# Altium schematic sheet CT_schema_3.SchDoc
size 573 x 363 mm
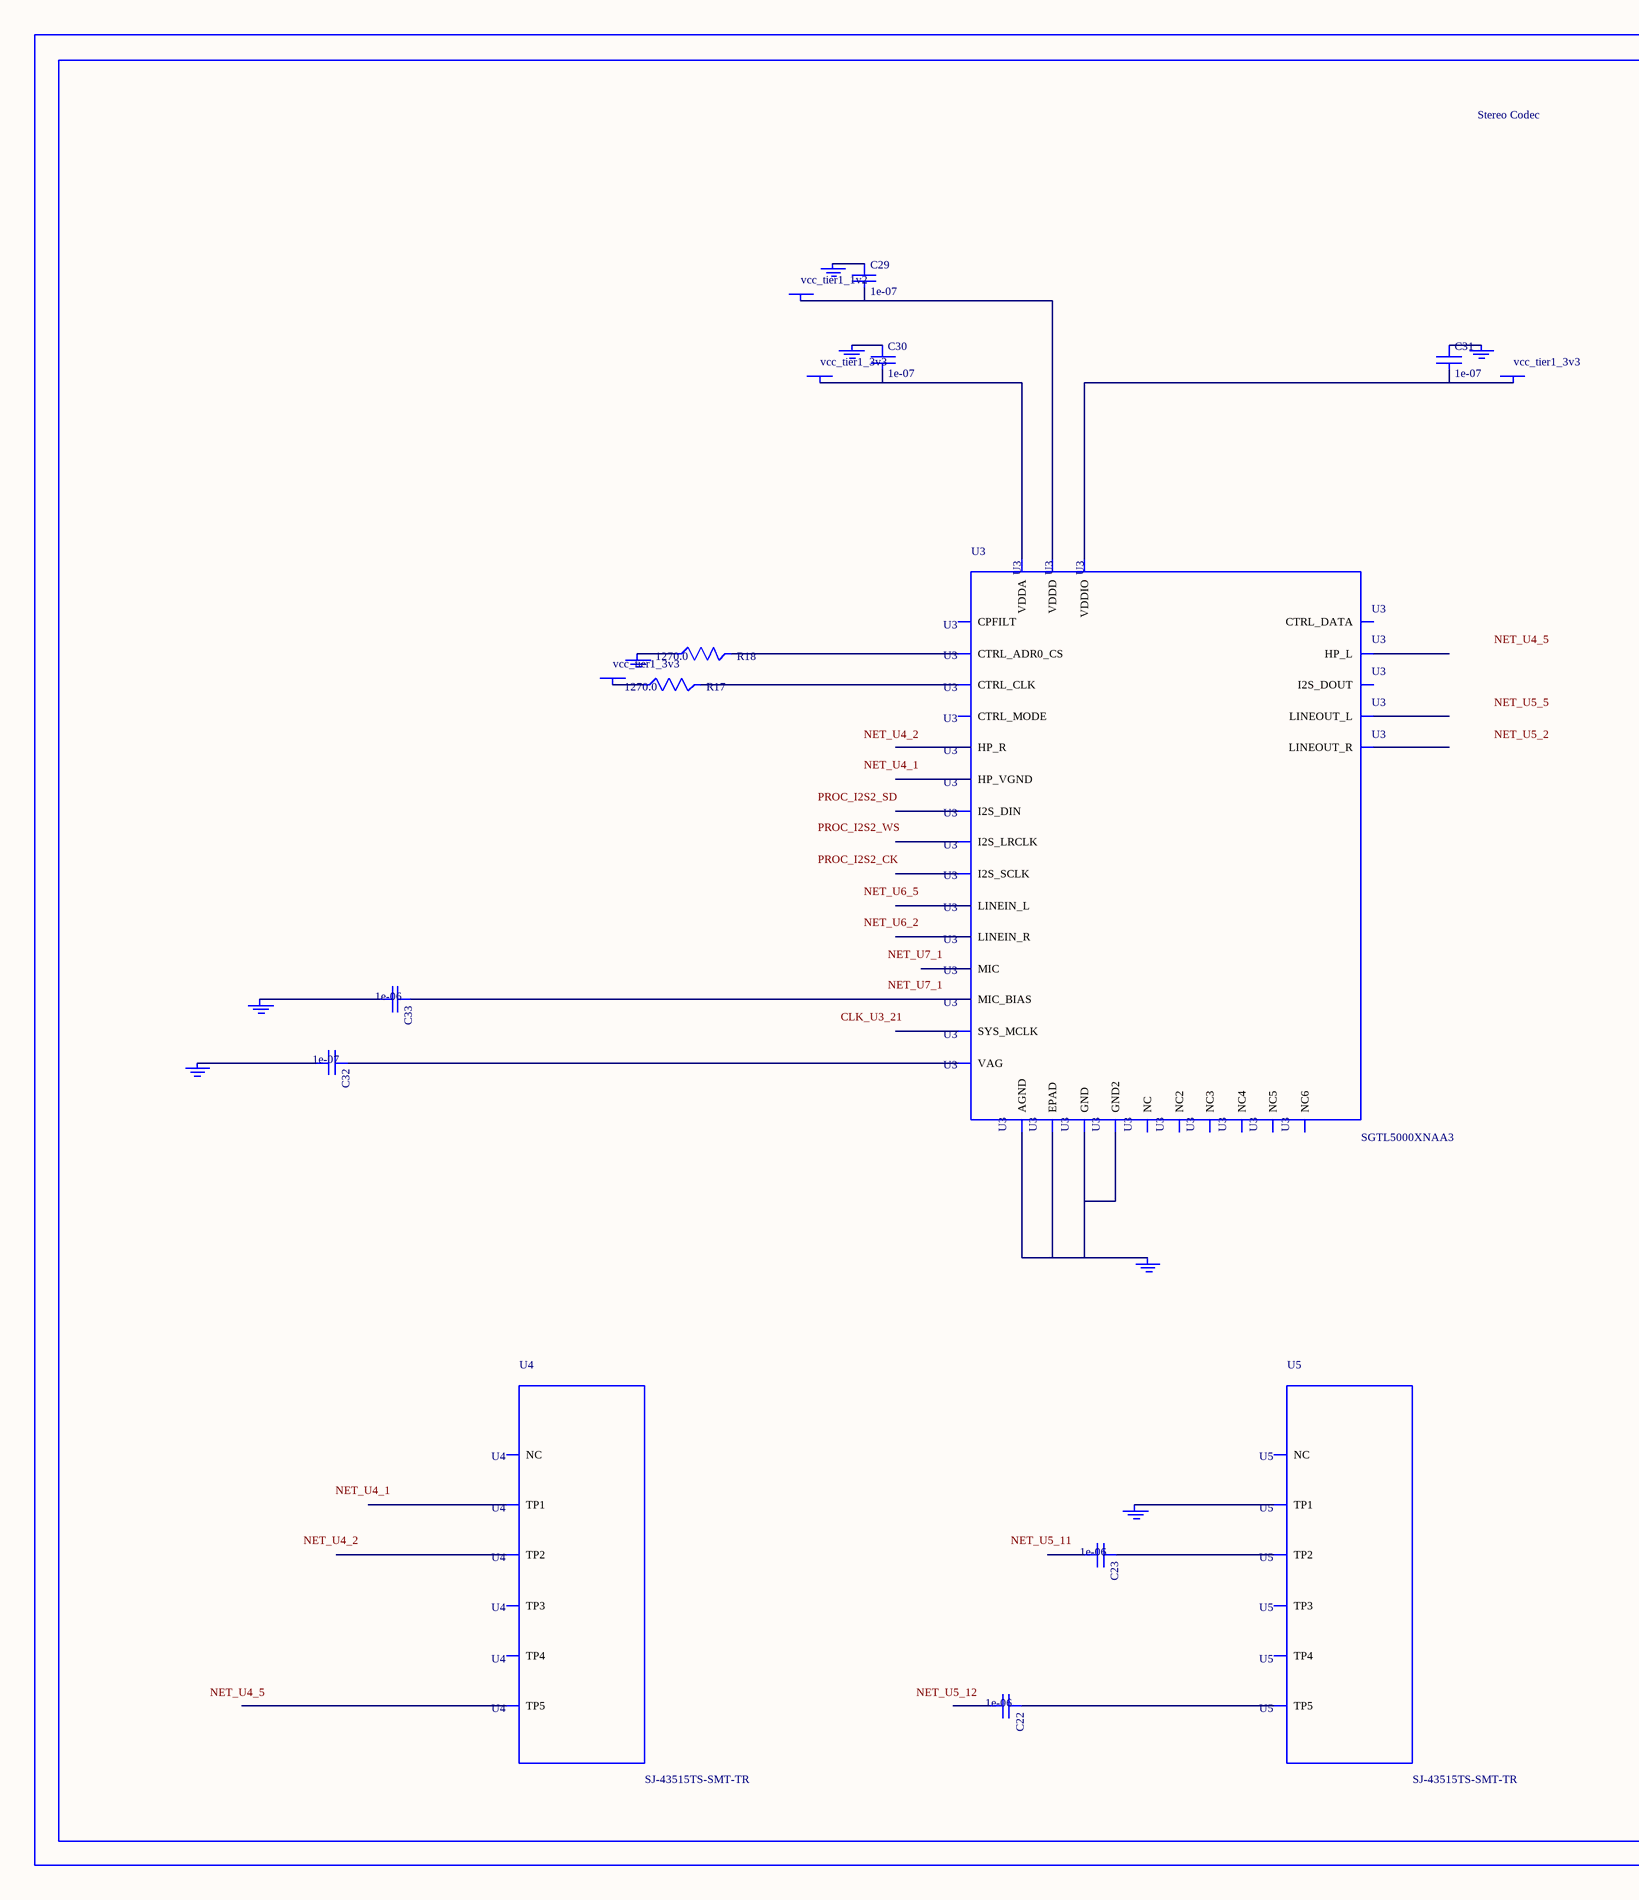
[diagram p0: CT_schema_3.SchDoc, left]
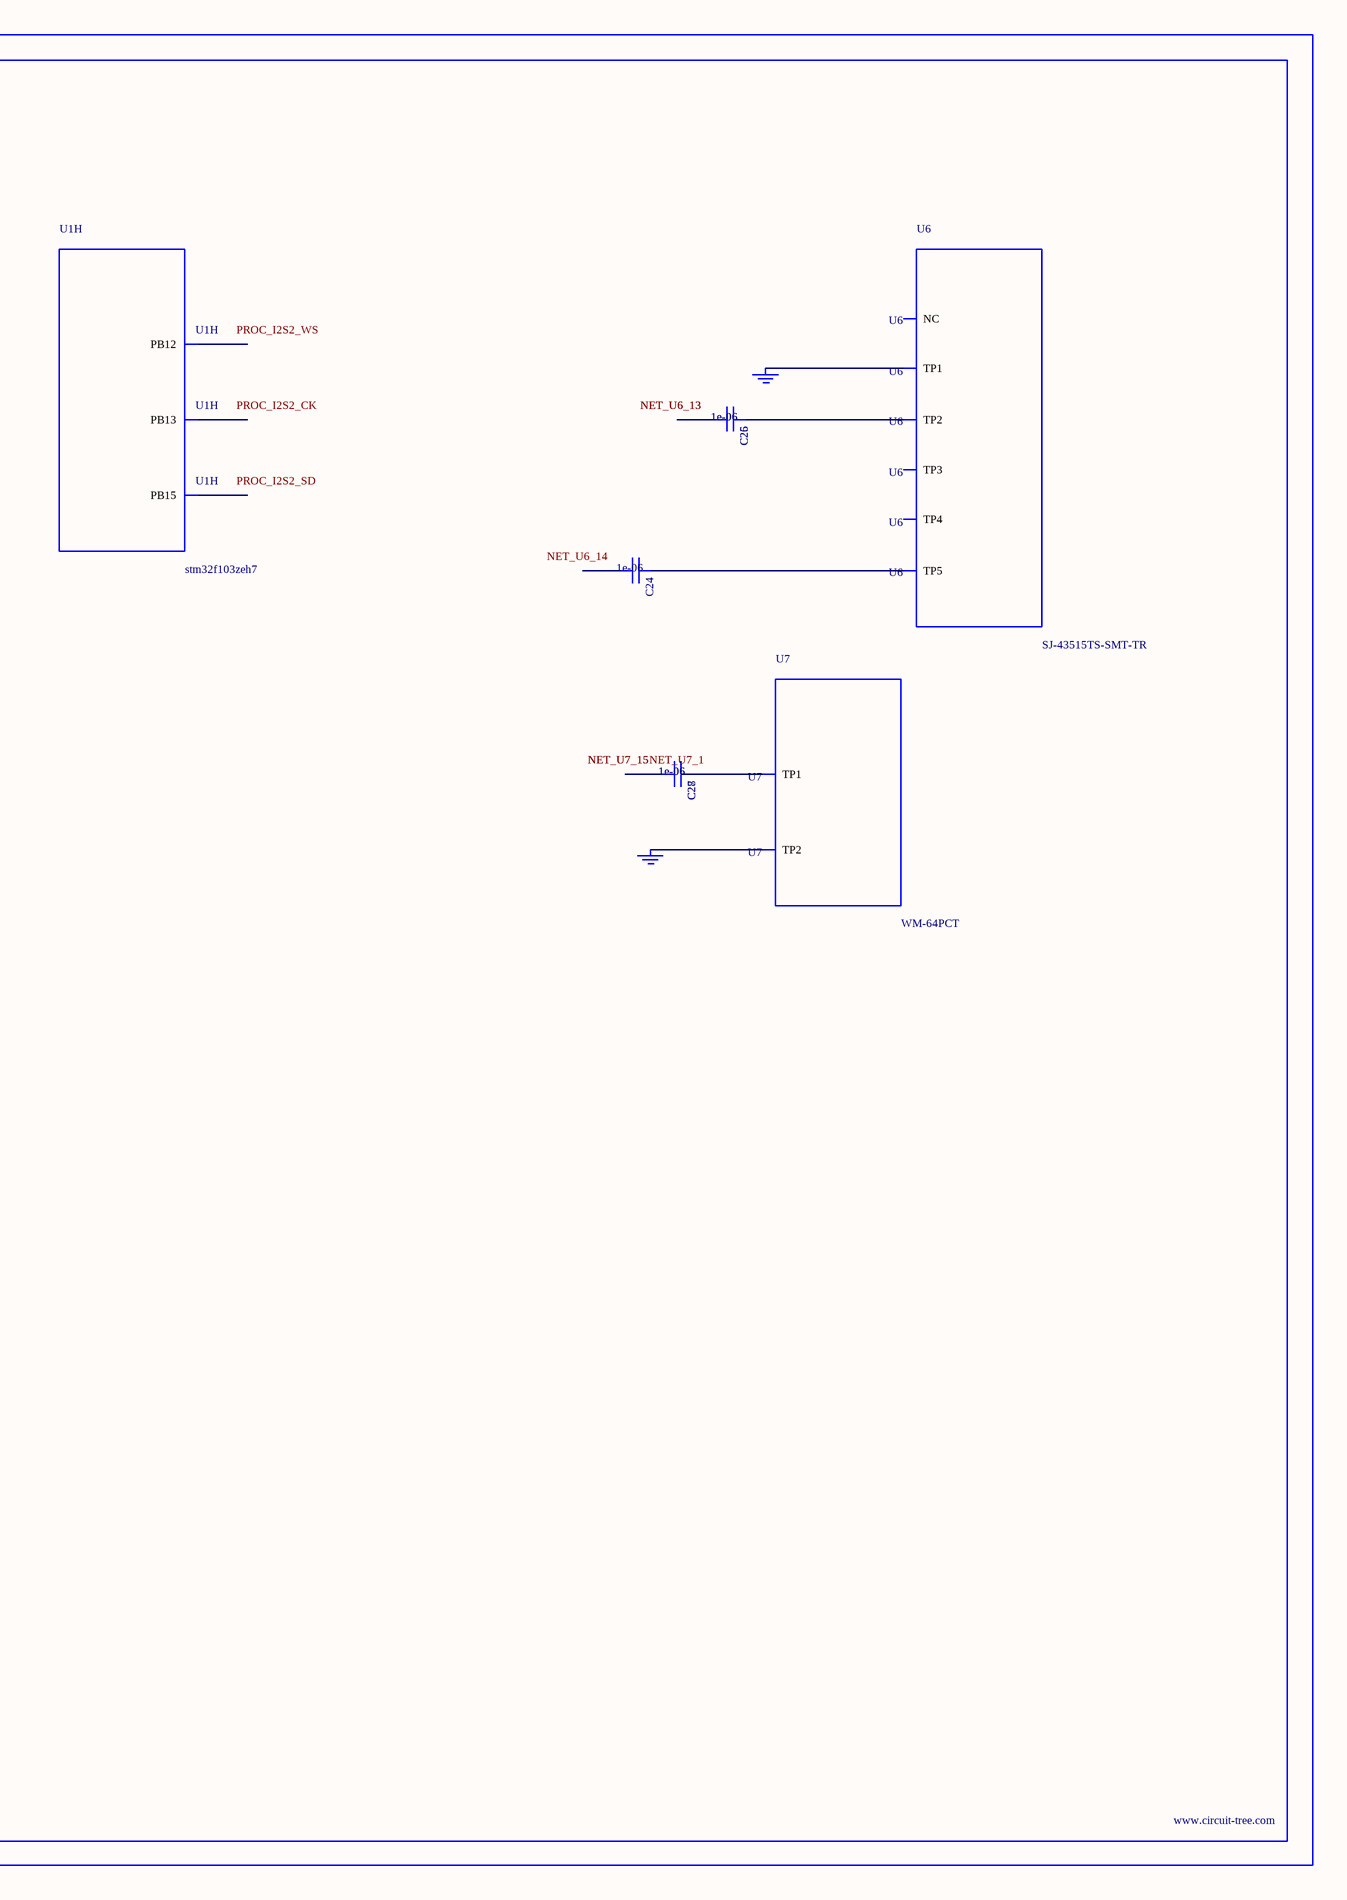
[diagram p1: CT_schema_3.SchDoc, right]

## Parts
BORDER2  (no value)
C22  1e-06  [C0603]
C23  1e-06  [C0603]
C24  1e-06  [C0603]
C25  1e-06  [C0603]
C26  1e-06  [C0603]
C27  1e-06  [C0603]
C28  1e-06  [C0603]
C29  1e-07  [C0402]
C30  1e-07  [C0402]
C31  1e-07  [C0402]
C32  1e-07  [C0402]
C33  1e-06  [C0603]
GND_INSTANCE_2_0  (no value)
GND_INSTANCE_2_1  (no value)
GND_INSTANCE_2_2  (no value)
GND_INSTANCE_2_3  (no value)
GND_INSTANCE_2_4  (no value)
GND_INSTANCE_2_5  (no value)
GND_INSTANCE_2_6  (no value)
GND_INSTANCE_2_7  (no value)
GND_INSTANCE_2_8  (no value)
GND_INSTANCE_2_9  (no value)
GND_INSTANCE_2_10  (no value)
POWER_INSTANCE_2_0  vcc_tier1_3v3
POWER_INSTANCE_2_1  vcc_tier1_3v3
POWER_INSTANCE_2_2  vcc_tier1_3v3
POWER_INSTANCE_2_3  vcc_tier1_1v2
R17  1270.0  [R0603]
R18  1270.0  [R0603]
U1  stm32f103zeh7  [LFBGA144]  (part H of 10)
U3  SGTL5000XNAA3  [QFN-32]
U4  SJ-43515TS-SMT-TR  [SJ-43515TS-SMT-TR]
U5  SJ-43515TS-SMT-TR  [SJ-43515TS-SMT-TR]
U6  SJ-43515TS-SMT-TR  [SJ-43515TS-SMT-TR]
U7  WM-64PCT  [WM-64PC]

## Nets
NetC22_1: C22.1 U5.5(TP5)
NetC23_1: C23.1 U5.2(TP2)
NetC24_1: C24.1 U6.5(TP5)
NetC25_1: C25.1 C26.1 U6.2(TP2)
NetC25_2: C25.2 C26.2
NetC27_1: C27.1 C28.1 U7.1(TP1)
NetC27_2: C27.2 C28.2
NetC29_1: C29.1 GND_INSTANCE_2_5.0(GND)
NetC29_2: C29.2 POWER_INSTANCE_2_3.0(PWR) U3.30(VDDD)
NetC30_1: C30.1 GND_INSTANCE_2_1.0(GND)
NetC30_2: C30.2 POWER_INSTANCE_2_0.0(PWR) U3.5(VDDA)
NetC31_1: C31.1 GND_INSTANCE_2_4.0(GND)
NetC31_2: C31.2 POWER_INSTANCE_2_1.0(PWR) U3.20(VDDIO)
NetC32_1: C32.1 U3.10(VAG)
NetC32_2: C32.2 GND_INSTANCE_2_2.0(GND)
NetC33_1: C33.1 U3.16(MIC_BIAS)
NetC33_2: C33.2 GND_INSTANCE_2_3.0(GND)
NetGND_INSTANCE_2_0_0: GND_INSTANCE_2_0.0(GND) U3.1(GND) U3.3(GND2) U3.7(AGND) U3.EXP(EPAD)
NetGND_INSTANCE_2_6_0: GND_INSTANCE_2_6.0(GND) R18.1
NetGND_INSTANCE_2_7_0: GND_INSTANCE_2_7.0(GND) U5.1(TP1)
NetGND_INSTANCE_2_8_0: GND_INSTANCE_2_8.0(GND) GND_INSTANCE_2_9.0(GND) U6.1(TP1)
NetGND_INSTANCE_2_10_0: GND_INSTANCE_2_10.0(GND) U7.2(TP2)
NetPOWER_INSTANCE_2_2_0: POWER_INSTANCE_2_2.0(PWR) R17.1
NetR17_2: R17.2 U3.29(CTRL_CLK)
NetR18_2: R18.2 U3.31(CTRL_ADR0_CS)

Not connected (* = marked no-connect by the designer): C22 2; C23 2; C24 2; U1 L12(PB15) M11(PB12) M12(PB13); U3 2(HP_R) 4(HP_VGND) 6(HP_L) 8(NC) 9(NC2) 11(LINEOUT_R) 12(LINEOUT_L) 13(LINEIN_R) 14(LINEIN_L) 15(MIC) 17(NC3) 18(CPFILT) 19(NC4) 21(SYS_MCLK) 22(NC5) 23(I2S_LRCLK) 24(I2S_SCLK) 25(I2S_DOUT) 26(I2S_DIN) 27(CTRL_DATA) 28(NC6) 32(CTRL_MODE); U4 1(TP1) 2(TP2) 3(TP3) 4(TP4) 5(TP5) 6(NC); U5 3(TP3) 4(TP4) 6(NC); U6 3(TP3) 4(TP4) 6(NC)

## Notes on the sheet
- Labels drawn without touching a wire or pin: CLK_U3_21, NET_U4_1, NET_U4_2, NET_U4_5, NET_U5_2, NET_U5_5, NET_U5_11, NET_U5_12, NET_U6_2, NET_U6_5, NET_U6_14, NET_U7_1, PROC_I2S2_CK, PROC_I2S2_SD, PROC_I2S2_WS

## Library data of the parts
BORDER2 = BORDER_PAGE2
C22-C28 C33 = C0603C105K3RACTU
C29-C32 = C0402C104K3RACTU
GND_INSTANCE_2_0-GND_INSTANCE_2_10 = GND
POWER_INSTANCE_2_0-POWER_INSTANCE_2_3 = PWR
R17 R18 = RC0603FR-071K27L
